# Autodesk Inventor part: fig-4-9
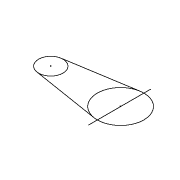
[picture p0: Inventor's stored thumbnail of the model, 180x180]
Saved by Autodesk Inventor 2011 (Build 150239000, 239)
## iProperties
Created: 2005-02
Part Number: fig-4-9
Document SubType Name: Modeling
Designer: CADCIM
Manufacturer: Standard
Standards Organization: Custom
Density: 1 g/cm^3
Author: CADCIM
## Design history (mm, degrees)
sketch "Sketch1"
  geometry: L1 (-28.496, 15.735)-(10.446, 21.986); L2 (-28.503, 2.004)-(10.432, -4.291); L3 (12.58, 26.117)-(12.58, -9.642); A1 r 6.954 centre (-27.393, 8.869) between (-28.496, 15.735) and (-28.503, 2.004); A2 r 13.308 centre (12.555, 8.846) between (10.446, 21.986) and (10.432, -4.291)
  constraints: 6 end point, 4 point on circle, 4 tangent, 2 centre point, 1 vertical, 1 other
